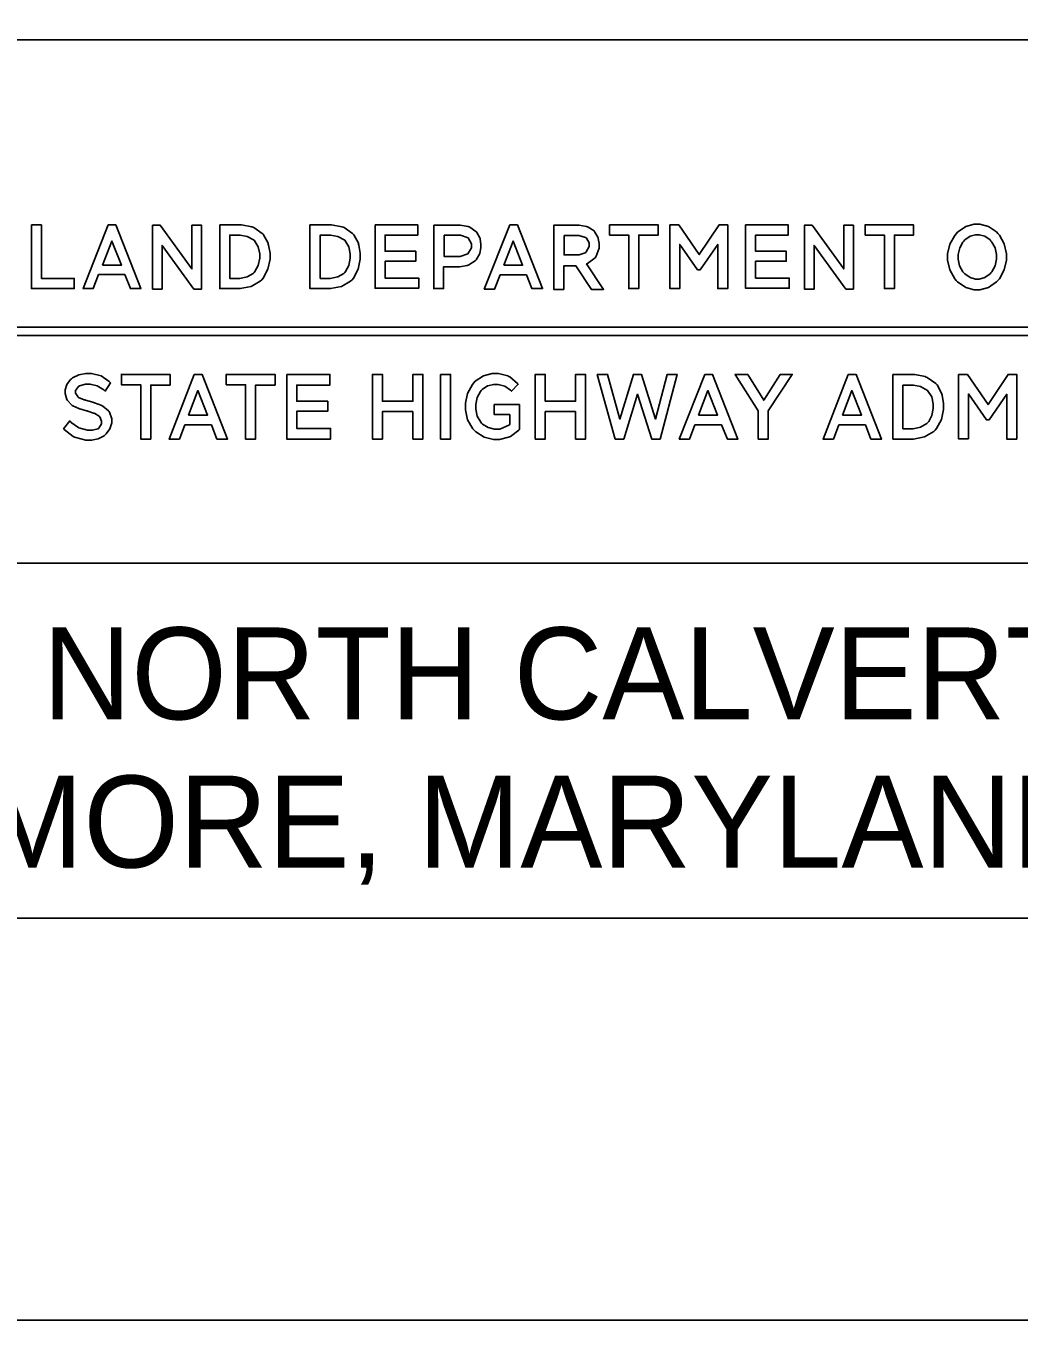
# Model space of a CAD drawing. Extents: x -1 to 9.2, y 0 to 14.8.
# Drawn here: x 3.799 to 4.663, y 0 to 1.127 of the extents above; entities that cross this region are included whole.
import ezdxf

# ---------------------------------------------------------------- set-up
doc = ezdxf.new("R2010")
doc.units = 0
for name, color, linetype in [('BORD-LINE', 7, 'Continuous'), ('MSHA-LOGO', 7, 'Continuous'), ('USER-LINE', 7, 'Continuous'), ('USER-PAGE', 7, 'Continuous')]:
    doc.layers.add(name, color=color, linetype=linetype)

msp = doc.modelspace()

# ---------------------------------------------------------------- linework, layer by layer
at = {"layer": 'BORD-LINE'}
msp.add_lwpolyline([(0.35, 0.8607), (0.35, 0.35), (8.15, 0.35), (8.15, 10.65), (0.35, 10.65), (0.35, 0.8607)], dxfattribs=at)
at = {"layer": 'MSHA-LOGO'}
for points in [[(3.8038, 0.9534), (3.8125, 0.9534), (3.8125, 0.9068), (3.841, 0.9068), (3.841, 0.8979), (3.8038, 0.8979)], [(3.8706, 0.9534), (3.8772, 0.9534), (3.8991, 0.8979), (3.8899, 0.8979), (3.885, 0.9102), (3.8622, 0.9102), (3.8574, 0.8979), (3.8487, 0.8979)], [(3.9452, 0.8976), (3.9175, 0.9356), (3.9175, 0.8976), (3.9092, 0.8976), (3.9092, 0.9531), (3.9158, 0.9531), (3.9434, 0.9151), (3.9434, 0.9531), (3.9518, 0.9531), (3.9518, 0.8976)], [(3.9676, 0.9534), (3.9831, 0.9534), (3.9865, 0.9534), (3.9955, 0.9518), (3.9964, 0.9514), (3.9973, 0.951), (4.0047, 0.946), (4.0053, 0.9454), (4.0058, 0.9447), (4.0097, 0.9375), (4.0099, 0.9367), (4.0101, 0.9359), (4.0114, 0.9287), (4.0114, 0.9263), (4.0114, 0.9235), (4.0096, 0.9149), (4.0054, 0.907), (4.0042, 0.9056), (4.0029, 0.9043), (3.9951, 0.8998), (3.9855, 0.8979), (3.9823, 0.8979), (3.9676, 0.8979)], [(4.0462, 0.9534), (4.0617, 0.9534), (4.065, 0.9534), (4.074, 0.9518), (4.075, 0.9514), (4.0759, 0.951), (4.0833, 0.946), (4.0839, 0.9454), (4.0844, 0.9447), (4.0883, 0.9375), (4.0885, 0.9367), (4.0887, 0.9359), (4.09, 0.9287), (4.09, 0.9263), (4.09, 0.9235), (4.0882, 0.9149), (4.084, 0.907), (4.0828, 0.9056), (4.0815, 0.9043), (4.0736, 0.8998), (4.0641, 0.8979), (4.0609, 0.8979), (4.0462, 0.8979)], [(4.1029, 0.9534), (4.14, 0.9534), (4.14, 0.9445), (4.1116, 0.9445), (4.1116, 0.9304), (4.1383, 0.9304), (4.1383, 0.9217), (4.1116, 0.9217), (4.1116, 0.9071), (4.1409, 0.9071), (4.1409, 0.8982), (4.1029, 0.8982)], [(4.1541, 0.8976), (4.1541, 0.9531), (4.1743, 0.9531), (4.1769, 0.9531), (4.1839, 0.9519), (4.1847, 0.9517), (4.1854, 0.9514), (4.1906, 0.9478), (4.191, 0.9474), (4.1914, 0.9469), (4.194, 0.9421), (4.1942, 0.9416), (4.1943, 0.9411), (4.195, 0.9365), (4.195, 0.935), (4.195, 0.9333), (4.1941, 0.9289), (4.1939, 0.9284), (4.1937, 0.9279), (4.1908, 0.9231), (4.1904, 0.9226), (4.1901, 0.9222), (4.1845, 0.9186), (4.1838, 0.9183), (4.1831, 0.918), (4.1763, 0.9169), (4.174, 0.9169), (4.1625, 0.9169), (4.1625, 0.8979), (4.1541, 0.8979)], [(4.2201, 0.9534), (4.2267, 0.9534), (4.2486, 0.8979), (4.2394, 0.8979), (4.2345, 0.9099), (4.2117, 0.9099), (4.2068, 0.8976), (4.1979, 0.8976)], [(4.2584, 0.8976), (4.2584, 0.9531), (4.2779, 0.9531), (4.2804, 0.9531), (4.287, 0.9519), (4.2877, 0.9517), (4.2884, 0.9515), (4.2934, 0.9481), (4.2938, 0.9477), (4.2941, 0.9472), (4.2967, 0.9427), (4.2969, 0.9422), (4.2971, 0.9417), (4.2978, 0.9371), (4.2978, 0.9356), (4.2978, 0.9331), (4.2954, 0.9262), (4.2949, 0.9255), (4.2944, 0.9248), (4.2877, 0.9197), (4.2869, 0.9195), (4.3018, 0.8973), (4.2912, 0.8973), (4.2776, 0.9177), (4.267, 0.9177), (4.267, 0.8973), (4.2584, 0.8973)], [(4.307, 0.9534), (4.3493, 0.9534), (4.3493, 0.9445), (4.3323, 0.9445), (4.3323, 0.8979), (4.3237, 0.8979), (4.3237, 0.9445), (4.307, 0.9445)], [(4.3594, 0.9534), (4.3672, 0.9534), (4.385, 0.9275), (4.4023, 0.9534), (4.4098, 0.9534), (4.4098, 0.8979), (4.4011, 0.8979), (4.4011, 0.9364), (4.3859, 0.9143), (4.3836, 0.9143), (4.368, 0.9364), (4.368, 0.8979), (4.3594, 0.8979)], [(4.4253, 0.9534), (4.4625, 0.9534), (4.4625, 0.9445), (4.434, 0.9445), (4.434, 0.9304), (4.4607, 0.9304), (4.4607, 0.9217), (4.434, 0.9217), (4.434, 0.9071), (4.4633, 0.9071), (4.4633, 0.8982), (4.4253, 0.8982)], [(4.5125, 0.8976), (4.4849, 0.9356), (4.4849, 0.8976), (4.4766, 0.8976), (4.4766, 0.9531), (4.4832, 0.9531), (4.5108, 0.9151), (4.5108, 0.9531), (4.5192, 0.9531), (4.5192, 0.8976)], [(4.5292, 0.9534), (4.5716, 0.9534), (4.5716, 0.9445), (4.5549, 0.9445), (4.5549, 0.8979), (4.5462, 0.8979), (4.5462, 0.9445), (4.5295, 0.9445), (4.5295, 0.9534)], [(4.6087, 0.9457), (4.6099, 0.947), (4.6169, 0.9519), (4.6243, 0.954), (4.6268, 0.954), (4.6293, 0.954), (4.6367, 0.952), (4.6437, 0.9473), (4.645, 0.9459), (4.6462, 0.9446), (4.6505, 0.9368), (4.6524, 0.9283), (4.6524, 0.9255), (4.6524, 0.9227), (4.6505, 0.9143), (4.6462, 0.9064), (4.645, 0.9051), (4.6437, 0.9037), (4.6367, 0.899), (4.6293, 0.897), (4.6268, 0.897), (4.6243, 0.897), (4.6169, 0.899), (4.6099, 0.9037), (4.6087, 0.9051), (4.6075, 0.9064), (4.6031, 0.9142), (4.6012, 0.9227), (4.6012, 0.9255), (4.6012, 0.9283), (4.6031, 0.9366), (4.6075, 0.9443)], [(3.8657, 0.9183), (3.8821, 0.9183), (3.8738, 0.9393)], [(3.9763, 0.9442), (3.9763, 0.9068), (3.9829, 0.9068), (3.985, 0.9068), (3.9915, 0.9081), (3.9967, 0.9111), (3.9975, 0.912), (3.9983, 0.9128), (4.0012, 0.9182), (4.0024, 0.9243), (4.0024, 0.9263), (4.0024, 0.9283), (4.0012, 0.9343), (3.9976, 0.94), (3.9916, 0.9434), (3.9853, 0.9445), (3.9831, 0.9445), (3.9763, 0.9445)], [(4.0551, 0.9442), (4.0551, 0.9068), (4.0617, 0.9068), (4.0639, 0.9068), (4.0704, 0.9081), (4.0756, 0.9111), (4.0764, 0.912), (4.0772, 0.9128), (4.0801, 0.9182), (4.0813, 0.9243), (4.0813, 0.9263), (4.0813, 0.9283), (4.0801, 0.9343), (4.0765, 0.94), (4.0705, 0.9434), (4.0641, 0.9445), (4.062, 0.9445), (4.0551, 0.9445)], [(4.1631, 0.9445), (4.1631, 0.9258), (4.1746, 0.9258), (4.1768, 0.9258), (4.1837, 0.9282), (4.1867, 0.9335), (4.1867, 0.9353), (4.1867, 0.937), (4.1838, 0.9422), (4.1773, 0.9445), (4.1752, 0.9445)], [(4.2149, 0.9183), (4.2313, 0.9183), (4.223, 0.9393)], [(4.2673, 0.9442), (4.2673, 0.9272), (4.2785, 0.9272), (4.2804, 0.9272), (4.2858, 0.9292), (4.2863, 0.9295), (4.2867, 0.9299), (4.2892, 0.9346), (4.2892, 0.9361), (4.2892, 0.9377), (4.287, 0.9418), (4.2866, 0.9422), (4.2861, 0.9425), (4.2802, 0.9442), (4.2782, 0.9442)], [(4.6153, 0.9117), (4.6161, 0.9108), (4.6207, 0.9075), (4.6255, 0.9062), (4.6271, 0.9062), (4.6287, 0.9062), (4.6335, 0.9075), (4.6381, 0.9108), (4.6389, 0.9117), (4.6397, 0.9126), (4.6425, 0.9177), (4.6438, 0.9236), (4.6438, 0.9255), (4.6438, 0.9275), (4.6425, 0.9333), (4.6397, 0.9385), (4.6389, 0.9393), (4.6381, 0.9403), (4.6335, 0.9435), (4.6287, 0.9448), (4.6271, 0.9448), (4.6255, 0.9448), (4.6207, 0.9435), (4.6161, 0.9403), (4.6153, 0.9393), (4.6145, 0.9385), (4.6117, 0.9333), (4.6104, 0.9275), (4.6104, 0.9255), (4.6104, 0.9236), (4.6115, 0.9177), (4.6144, 0.9126)], [(3.5786, 0.8643), (5.4382, 0.8643), (5.4382, 0.8571), (3.5786, 0.8571)], [(3.8629, 0.7866), (3.8626, 0.7869), (3.8589, 0.7892), (3.8584, 0.7895), (3.8579, 0.7896), (3.8528, 0.7913), (3.8522, 0.7914), (3.8516, 0.7916), (3.846, 0.7932), (3.8455, 0.7934), (3.8449, 0.7936), (3.8398, 0.7959), (3.8393, 0.7962), (3.8388, 0.7965), (3.8351, 0.8005), (3.8348, 0.801), (3.8345, 0.8015), (3.8331, 0.8066), (3.8331, 0.8083), (3.8331, 0.8098), (3.8346, 0.8144), (3.8378, 0.8188), (3.8387, 0.8195), (3.8396, 0.8203), (3.845, 0.8229), (3.8511, 0.824), (3.8531, 0.824), (3.8559, 0.824), (3.8643, 0.822), (3.8715, 0.8172), (3.8727, 0.8159), (3.868, 0.8088), (3.8669, 0.8098), (3.861, 0.8133), (3.8548, 0.8147), (3.8528, 0.8147), (3.8509, 0.8147), (3.8457, 0.8134), (3.8452, 0.8131), (3.8447, 0.8128), (3.8421, 0.8092), (3.8421, 0.808), (3.8421, 0.8069), (3.844, 0.8039), (3.8444, 0.8035), (3.8447, 0.8032), (3.8496, 0.8011), (3.8503, 0.801), (3.8509, 0.8009), (3.8571, 0.799), (3.8578, 0.7987), (3.8585, 0.7985), (3.8649, 0.7961), (3.8654, 0.7959), (3.866, 0.7956), (3.8709, 0.7914), (3.8713, 0.7909), (3.8717, 0.7903), (3.8736, 0.7846), (3.8736, 0.7827), (3.8736, 0.7811), (3.8721, 0.776), (3.8689, 0.7714), (3.868, 0.7706), (3.867, 0.7699), (3.8617, 0.7671), (3.8561, 0.7659), (3.8542, 0.7659), (3.851, 0.7659), (3.8423, 0.7682), (3.8413, 0.7687), (3.8402, 0.7692), (3.8323, 0.7753), (3.8317, 0.776), (3.8371, 0.7827), (3.8382, 0.7814), (3.8449, 0.7766), (3.8525, 0.7746), (3.855, 0.7746), (3.8568, 0.7746), (3.8616, 0.776), (3.8621, 0.7763), (3.8625, 0.7765), (3.8646, 0.7801), (3.8646, 0.7813), (3.8646, 0.7826), (3.8632, 0.7864)], [(3.8817, 0.8232), (3.9244, 0.8232), (3.9244, 0.8139), (3.9076, 0.8139), (3.9076, 0.767), (3.8989, 0.767), (3.8989, 0.8142), (3.882, 0.8142), (3.882, 0.8232)], [(3.9455, 0.8232), (3.9523, 0.8232), (3.9745, 0.767), (3.9652, 0.767), (3.9604, 0.7793), (3.9374, 0.7793), (3.9326, 0.767), (3.9236, 0.767)], [(3.973, 0.8232), (4.0158, 0.8232), (4.0158, 0.8139), (3.9989, 0.8139), (3.9989, 0.767), (3.9902, 0.767), (3.9902, 0.8142), (3.9733, 0.8142), (3.9733, 0.8232)], [(4.0259, 0.8232), (4.0635, 0.8232), (4.0635, 0.8139), (4.0346, 0.8139), (4.0346, 0.7999), (4.0616, 0.7999), (4.0616, 0.7912), (4.0346, 0.7912), (4.0346, 0.7763), (4.0641, 0.7763), (4.0641, 0.767), (4.0259, 0.767)], [(4.1358, 0.7909), (4.1093, 0.7909), (4.1093, 0.767), (4.1006, 0.767), (4.1006, 0.8232), (4.1093, 0.8232), (4.1093, 0.7999), (4.1358, 0.7999), (4.1358, 0.8232), (4.1445, 0.8232), (4.1445, 0.767), (4.1358, 0.767)], [(4.1599, 0.8232), (4.1686, 0.8232), (4.1686, 0.767), (4.1599, 0.767)], [(4.2066, 0.797), (4.2285, 0.797), (4.2285, 0.7754), (4.2279, 0.7747), (4.2206, 0.7693), (4.2198, 0.7689), (4.2189, 0.7685), (4.2111, 0.7667), (4.2085, 0.7667), (4.2058, 0.7667), (4.1978, 0.7686), (4.1904, 0.7732), (4.1891, 0.7746), (4.1879, 0.7759), (4.1834, 0.7837), (4.1816, 0.7925), (4.1816, 0.7954), (4.1816, 0.7982), (4.1834, 0.8066), (4.1877, 0.8145), (4.1889, 0.8159), (4.1901, 0.8173), (4.1973, 0.8221), (4.2049, 0.824), (4.2074, 0.824), (4.2103, 0.824), (4.2183, 0.8219), (4.2192, 0.8215), (4.2201, 0.8211), (4.2269, 0.8154), (4.2274, 0.8147), (4.2215, 0.8086), (4.2207, 0.8096), (4.2158, 0.813), (4.2099, 0.8145), (4.208, 0.8145), (4.2062, 0.8145), (4.2008, 0.8132), (4.1961, 0.81), (4.1953, 0.8091), (4.1946, 0.8083), (4.1918, 0.8031), (4.1905, 0.7971), (4.1905, 0.7951), (4.1905, 0.7931), (4.1918, 0.787), (4.1948, 0.7817), (4.1956, 0.7807), (4.1964, 0.7799), (4.2013, 0.777), (4.2067, 0.7757), (4.2085, 0.7757), (4.2114, 0.7757), (4.2193, 0.779), (4.2201, 0.7796), (4.2201, 0.7883), (4.2066, 0.7883)], [(4.2774, 0.7909), (4.251, 0.7909), (4.251, 0.767), (4.2423, 0.767), (4.2423, 0.8232), (4.251, 0.8232), (4.251, 0.7999), (4.2774, 0.7999), (4.2774, 0.8232), (4.2861, 0.8232), (4.2861, 0.767), (4.2774, 0.767)], [(4.351, 0.767), (4.3437, 0.767), (4.3313, 0.806), (4.3193, 0.767), (4.3119, 0.767), (4.2962, 0.8232), (4.3052, 0.8232), (4.3159, 0.7844), (4.3277, 0.8232), (4.3347, 0.8232), (4.3468, 0.7844), (4.3572, 0.8232), (4.3659, 0.8232)], [(4.3898, 0.8232), (4.3965, 0.8232), (4.4187, 0.767), (4.4095, 0.767), (4.4044, 0.7793), (4.3813, 0.7793), (4.3766, 0.767), (4.3676, 0.767)], [(4.4451, 0.7914), (4.4451, 0.767), (4.4364, 0.767), (4.4364, 0.7914), (4.4162, 0.8232), (4.4272, 0.8232), (4.4412, 0.8007), (4.4555, 0.8232), (4.4659, 0.8232)], [(4.5147, 0.8232), (4.5215, 0.8232), (4.5437, 0.767), (4.5344, 0.767), (4.5296, 0.7793), (4.5066, 0.7793), (4.5018, 0.767), (4.4928, 0.767)], [(4.5535, 0.8232), (4.5692, 0.8232), (4.5725, 0.8232), (4.5815, 0.8213), (4.5825, 0.8209), (4.5834, 0.8206), (4.5909, 0.8154), (4.5914, 0.8147), (4.592, 0.8141), (4.5959, 0.8069), (4.5962, 0.806), (4.5965, 0.8052), (4.5976, 0.798), (4.5976, 0.7956), (4.5976, 0.7928), (4.5958, 0.7841), (4.5915, 0.7762), (4.5903, 0.7748), (4.5891, 0.7735), (4.5812, 0.7689), (4.5716, 0.767), (4.5684, 0.767), (4.5535, 0.767)], [(4.6106, 0.8232), (4.6184, 0.8232), (4.6364, 0.797), (4.6538, 0.8232), (4.6614, 0.8232), (4.6614, 0.767), (4.6527, 0.767), (4.6527, 0.806), (4.6373, 0.7838), (4.635, 0.7838), (4.6193, 0.8063), (4.6193, 0.7673), (4.6106, 0.7673)], [(4.5622, 0.8139), (4.5622, 0.776), (4.569, 0.776), (4.5711, 0.776), (4.5777, 0.7773), (4.583, 0.7804), (4.5839, 0.7813), (4.5847, 0.7822), (4.5875, 0.7876), (4.5886, 0.7937), (4.5886, 0.7956), (4.5886, 0.7976), (4.5874, 0.8036), (4.5838, 0.8093), (4.5777, 0.8128), (4.5714, 0.8139), (4.5692, 0.8139)], [(3.9405, 0.7878), (3.957, 0.7878), (3.9486, 0.8091)], [(4.3844, 0.7878), (4.401, 0.7878), (4.3926, 0.8091)], [(4.5097, 0.7878), (4.5263, 0.7878), (4.5178, 0.8091)]]:
    msp.add_lwpolyline(points, close=True, dxfattribs=at)
at = {"layer": 'USER-LINE'}
msp.add_lwpolyline([(5.5468, 0.6588), (2.9468, 0.6588), (2.9468, 1.1144), (5.5468, 1.1144)], close=True, dxfattribs=at)
at = {"layer": 'USER-PAGE'}
msp.add_lwpolyline([(0, 11), (8.5, 11), (8.5, 0), (0, 0)], close=True, dxfattribs=at)

# ---------------------------------------------------------------- texts
at = {"layer": 'BORD-LINE'}
for s, p in [('707 NORTH CALVERT ST.', (3.6052, 0.523)), ('BALTIMORE, MARYLAND 21202', (3.4626, 0.394))]:
    msp.add_text(s, height=0.079998, dxfattribs=at).set_placement(p)

doc.saveas('drawing.dxf')
